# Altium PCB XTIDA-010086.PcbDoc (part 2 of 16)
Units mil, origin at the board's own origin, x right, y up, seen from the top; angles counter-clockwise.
Board outline 14763.78 x 8267.72 mil, 6 copper layers (Top Layer, GND Layer, Signal Layer 1, Signal Layer 2, Power Layer, Bottom Layer), stack 62 mil thick; 1933 components, 1002 nets, 4886 pads, 6482 vias.
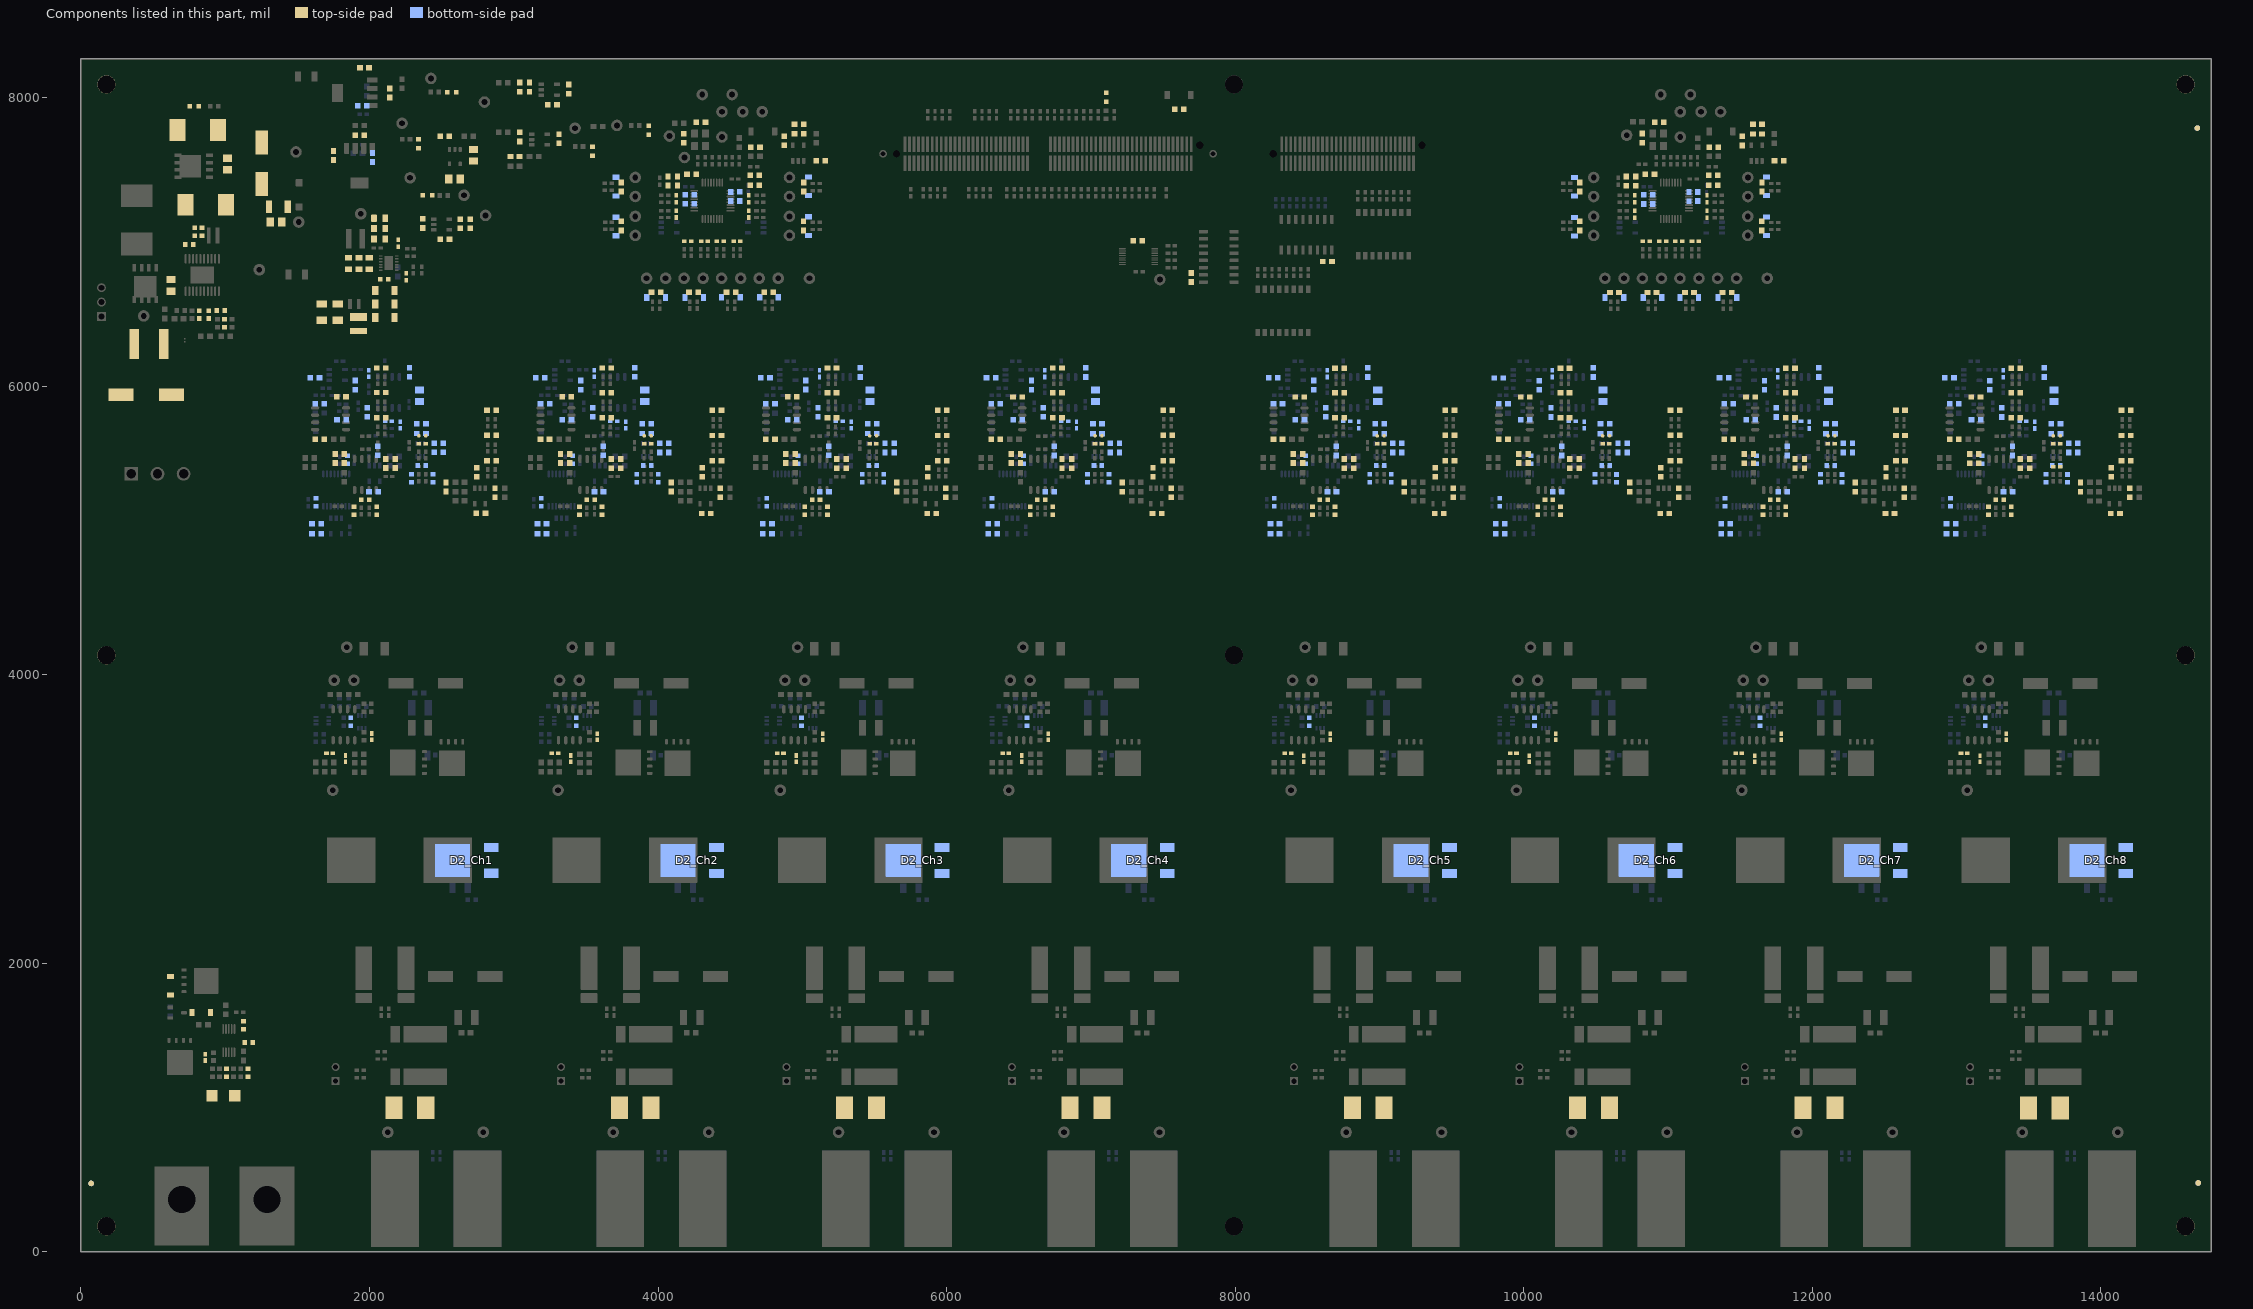
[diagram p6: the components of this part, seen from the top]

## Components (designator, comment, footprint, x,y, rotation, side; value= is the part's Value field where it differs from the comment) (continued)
C16_Ch8 "GCM155R71E103KA37D" 0402 13693.7,5442.01 r180 top value=0.01uF (schematic designator C16)
C17_Ch1 "GCM155R71E103KA37D" 0402 2366,5601.05 r180 top value=0.01uF (schematic designator C17)
C17_Ch2 "GCM155R71E103KA37D" 0402 3928,5600.97 r180 top value=0.01uF (schematic designator C17)
C17_Ch3 "GCM155R71E103KA37D" 0402 5490,5600.89 r180 top value=0.01uF (schematic designator C17)
C17_Ch4 "GCM155R71E103KA37D" 0402 7052,5600.81 r180 top value=0.01uF (schematic designator C17)
C17_Ch5 "GCM155R71E103KA37D" 0402 9007.7,5600.73 r180 top value=0.01uF (schematic designator C17)
C17_Ch6 "GCM155R71E103KA37D" 0402 10569.7,5600.65 r180 top value=0.01uF (schematic designator C17)
C17_Ch7 "GCM155R71E103KA37D" 0402 12131.7,5600.57 r180 top value=0.01uF (schematic designator C17)
C17_Ch8 "GCM155R71E103KA37D" 0402 13693.7,5600.5 r180 top value=0.01uF (schematic designator C17)
C18_Ch1 "Capacitor" 0603 2180,5463.05 r270 top value=1uF (schematic designator C18)
C18_Ch2 "Capacitor" 0603 3742,5462.97 r270 top value=1uF (schematic designator C18)
C18_Ch3 "Capacitor" 0603 5304,5462.89 r270 top value=1uF (schematic designator C18)
C18_Ch4 "Capacitor" 0603 6866,5462.81 r270 top value=1uF (schematic designator C18)
C18_Ch5 "Capacitor" 0603 8821.7,5462.73 r270 top value=1uF (schematic designator C18)
C18_Ch6 "Capacitor" 0603 10383.7,5462.65 r270 top value=1uF (schematic designator C18)
C18_Ch7 "Capacitor" 0603 11945.7,5462.57 r270 top value=1uF (schematic designator C18)
C18_Ch8 "Capacitor" 0603 13507.7,5462.5 r270 top value=1uF (schematic designator C18)
C19_Ch1 "GRM1885C1H102JA01D" 0603L 1971,5212.05 r0 top value=1000pF (schematic designator C19)
C19_Ch2 "GRM1885C1H102JA01D" 0603L 3533,5211.97 r0 top value=1000pF (schematic designator C19)
C19_Ch3 "GRM1885C1H102JA01D" 0603L 5095,5211.89 r0 top value=1000pF (schematic designator C19)
C19_Ch4 "GRM1885C1H102JA01D" 0603L 6657,5211.81 r0 top value=1000pF (schematic designator C19)
C19_Ch5 "GRM1885C1H102JA01D" 0603L 8612.7,5211.73 r0 top value=1000pF (schematic designator C19)
C19_Ch6 "GRM1885C1H102JA01D" 0603L 10174.7,5211.65 r0 top value=1000pF (schematic designator C19)
C19_Ch7 "GRM1885C1H102JA01D" 0603L 11736.7,5211.57 r0 top value=1000pF (schematic designator C19)
C19_Ch8 "GRM1885C1H102JA01D" 0603L 13298.7,5211.5 r0 top value=1000pF (schematic designator C19)
C20_Ch1 "Capacitor" 0603 2114,5463.05 r270 top value=0.1uF (schematic designator C20)
C20_Ch2 "Capacitor" 0603 3676,5462.97 r270 top value=0.1uF (schematic designator C20)
C20_Ch3 "Capacitor" 0603 5238,5462.89 r270 top value=0.1uF (schematic designator C20)
C20_Ch4 "Capacitor" 0603 6800,5462.81 r270 top value=0.1uF (schematic designator C20)
C20_Ch5 "Capacitor" 0603 8755.7,5462.73 r270 top value=0.1uF (schematic designator C20)
C20_Ch6 "Capacitor" 0603 10317.7,5462.65 r270 top value=0.1uF (schematic designator C20)
C20_Ch7 "Capacitor" 0603 11879.7,5462.57 r270 top value=0.1uF (schematic designator C20)
C20_Ch8 "Capacitor" 0603 13441.7,5462.5 r270 top value=0.1uF (schematic designator C20)
C21_Ch1 "GRM1885C1H101JA01D" 0603L 2050.2,5135.25 r90 top value=DNP (schematic designator C21)
C21_Ch2 "GRM1885C1H101JA01D" 0603L 3612.2,5135.17 r90 top value=DNP (schematic designator C21)
C21_Ch3 "GRM1885C1H101JA01D" 0603L 5174.2,5135.09 r90 top value=DNP (schematic designator C21)
C21_Ch4 "GRM1885C1H101JA01D" 0603L 6736.2,5135.01 r90 top value=DNP (schematic designator C21)
C21_Ch5 "GRM1885C1H101JA01D" 0603L 8691.91,5134.93 r90 top value=DNP (schematic designator C21)
C21_Ch6 "GRM1885C1H101JA01D" 0603L 10253.91,5134.85 r90 top value=DNP (schematic designator C21)
C21_Ch7 "GRM1885C1H101JA01D" 0603L 11815.91,5134.77 r90 top value=DNP (schematic designator C21)
C21_Ch8 "GRM1885C1H101JA01D" 0603L 13377.91,5134.7 r90 top value=DNP (schematic designator C21)
C22_Ch1 "GRM1885C1H101JA01D" 0603L 1893.2,5135.25 r270 top value=DNP (schematic designator C22)
C22_Ch2 "GRM1885C1H101JA01D" 0603L 3455.2,5135.17 r270 top value=DNP (schematic designator C22)
C22_Ch3 "GRM1885C1H101JA01D" 0603L 5017.2,5135.09 r270 top value=DNP (schematic designator C22)
C22_Ch4 "GRM1885C1H101JA01D" 0603L 6579.2,5135.01 r270 top value=DNP (schematic designator C22)
C22_Ch5 "GRM1885C1H101JA01D" 0603L 8534.91,5134.93 r270 top value=DNP (schematic designator C22)
C22_Ch6 "GRM1885C1H101JA01D" 0603L 10096.91,5134.85 r270 top value=DNP (schematic designator C22)
C22_Ch7 "GRM1885C1H101JA01D" 0603L 11658.91,5134.77 r270 top value=DNP (schematic designator C22)
C22_Ch8 "GRM1885C1H101JA01D" 0603L 13220.91,5134.7 r270 top value=DNP (schematic designator C22)
C23_Ch1 "Capacitor" 0603 1826,5498.05 r270 top value=0.1uF (schematic designator C23)
C23_Ch2 "Capacitor" 0603 3388,5497.97 r270 top value=0.1uF (schematic designator C23)
C23_Ch3 "Capacitor" 0603 4950,5497.89 r270 top value=0.1uF (schematic designator C23)
C23_Ch4 "Capacitor" 0603 6512,5497.81 r270 top value=0.1uF (schematic designator C23)
C23_Ch5 "Capacitor" 0603 8467.7,5497.73 r270 top value=0.1uF (schematic designator C23)
C23_Ch6 "Capacitor" 0603 10029.7,5497.65 r270 top value=0.1uF (schematic designator C23)
C23_Ch7 "Capacitor" 0603 11591.7,5497.57 r270 top value=0.1uF (schematic designator C23)
C23_Ch8 "Capacitor" 0603 13153.7,5497.5 r270 top value=0.1uF (schematic designator C23)
C24_Ch1 "Capacitor" 0603 1762,5498.05 r270 top value=1uF (schematic designator C24)
C24_Ch2 "Capacitor" 0603 3324,5497.97 r270 top value=1uF (schematic designator C24)
C24_Ch3 "Capacitor" 0603 4886,5497.89 r270 top value=1uF (schematic designator C24)
C24_Ch4 "Capacitor" 0603 6448,5497.81 r270 top value=1uF (schematic designator C24)
C24_Ch5 "Capacitor" 0603 8403.7,5497.73 r270 top value=1uF (schematic designator C24)
C24_Ch6 "Capacitor" 0603 9965.7,5497.65 r270 top value=1uF (schematic designator C24)
C24_Ch7 "Capacitor" 0603 11527.7,5497.57 r270 top value=1uF (schematic designator C24)
C24_Ch8 "Capacitor" 0603 13089.7,5497.5 r270 top value=1uF (schematic designator C24)
C25_Ch1 "C0603C103J3GECAUTO" 0603 2082,5780.05 r0 top value=0.01uF (schematic designator C25)
C25_Ch2 "C0603C103J3GECAUTO" 0603 3644,5779.97 r0 top value=0.01uF (schematic designator C25)
C25_Ch3 "C0603C103J3GECAUTO" 0603 5206,5779.89 r0 top value=0.01uF (schematic designator C25)
C25_Ch4 "C0603C103J3GECAUTO" 0603 6768,5779.81 r0 top value=0.01uF (schematic designator C25)
C25_Ch5 "C0603C103J3GECAUTO" 0603 8723.7,5779.73 r0 top value=0.01uF (schematic designator C25)
C25_Ch6 "C0603C103J3GECAUTO" 0603 10285.7,5779.65 r0 top value=0.01uF (schematic designator C25)
C25_Ch7 "C0603C103J3GECAUTO" 0603 11847.7,5779.57 r0 top value=0.01uF (schematic designator C25)
C25_Ch8 "C0603C103J3GECAUTO" 0603 13409.7,5779.5 r0 top value=0.01uF (schematic designator C25)
C26_Ch1 "C0603C103J3GECAUTO" 0603 2082,5955.05 r0 top value=0.01uF (schematic designator C26)
C26_Ch2 "C0603C103J3GECAUTO" 0603 3644,5954.97 r0 top value=0.01uF (schematic designator C26)
C26_Ch3 "C0603C103J3GECAUTO" 0603 5206,5954.89 r0 top value=0.01uF (schematic designator C26)
C26_Ch4 "C0603C103J3GECAUTO" 0603 6768,5954.81 r0 top value=0.01uF (schematic designator C26)
C26_Ch5 "C0603C103J3GECAUTO" 0603 8723.7,5954.73 r0 top value=0.01uF (schematic designator C26)
C26_Ch6 "C0603C103J3GECAUTO" 0603 10285.7,5954.65 r0 top value=0.01uF (schematic designator C26)
C26_Ch7 "C0603C103J3GECAUTO" 0603 11847.7,5954.57 r0 top value=0.01uF (schematic designator C26)
C26_Ch8 "C0603C103J3GECAUTO" 0603 13409.7,5954.5 r0 top value=0.01uF (schematic designator C26)
C27_Ch1 "C0603C103J3GECAUTO" 0603 2082,6125.05 r0 top value=0.01uF (schematic designator C27)
C27_Ch2 "C0603C103J3GECAUTO" 0603 3644,6124.97 r0 top value=0.01uF (schematic designator C27)
C27_Ch3 "C0603C103J3GECAUTO" 0603 5206,6124.89 r0 top value=0.01uF (schematic designator C27)
C27_Ch4 "C0603C103J3GECAUTO" 0603 6768,6124.81 r0 top value=0.01uF (schematic designator C27)
C27_Ch5 "C0603C103J3GECAUTO" 0603 8723.7,6124.73 r0 top value=0.01uF (schematic designator C27)
C27_Ch6 "C0603C103J3GECAUTO" 0603 10285.7,6124.65 r0 top value=0.01uF (schematic designator C27)
C27_Ch7 "C0603C103J3GECAUTO" 0603 11847.7,6124.57 r0 top value=0.01uF (schematic designator C27)
C27_Ch8 "C0603C103J3GECAUTO" 0603 13409.7,6124.5 r0 top value=0.01uF (schematic designator C27)
C28_Ch1 "C0603C103J3GECAUTO" 0603 3744.87,7379.63 r270 top value=0.01uF (schematic designator C28)
C28_Ch2 "C0603C103J3GECAUTO" 0603 3986.75,6649.05 r0 top value=0.01uF (schematic designator C28)
C28_Ch3 "C0603C103J3GECAUTO" 0603 4506.61,6649.05 r0 top value=0.01uF (schematic designator C28)
C28_Ch4 "C0603C103J3GECAUTO" 0603 5008.42,7110.03 r90 top value=0.01uF (schematic designator C28)
C28_Ch5 "C0603C103J3GECAUTO" 0603 10386.58,7379.32 r270 top value=0.01uF (schematic designator C28)
C28_Ch6 "C0603C103J3GECAUTO" 0603 10628.45,6648.73 r0 top value=0.01uF (schematic designator C28)
C28_Ch7 "C0603C103J3GECAUTO" 0603 11148.31,6648.73 r0 top value=0.01uF (schematic designator C28)
C28_Ch8 "C0603C103J3GECAUTO" 0603 11650.12,7109.71 r90 top value=0.01uF (schematic designator C28)
C29_Ch1 "Capacitor" 0603 2029,5268.05 r0 bottom value=0.1uF (schematic designator C29)
C29_Ch2 "Capacitor" 0603 3591,5267.97 r0 bottom value=0.1uF (schematic designator C29)
C29_Ch3 "Capacitor" 0603 5153,5267.89 r0 bottom value=0.1uF (schematic designator C29)
C29_Ch4 "Capacitor" 0603 6715,5267.81 r0 bottom value=0.1uF (schematic designator C29)
C29_Ch5 "Capacitor" 0603 8670.7,5267.73 r0 bottom value=0.1uF (schematic designator C29)
C29_Ch6 "Capacitor" 0603 10232.7,5267.65 r0 bottom value=0.1uF (schematic designator C29)
C29_Ch7 "Capacitor" 0603 11794.7,5267.57 r0 bottom value=0.1uF (schematic designator C29)
C29_Ch8 "Capacitor" 0603 13356.7,5267.5 r0 bottom value=0.1uF (schematic designator C29)
C30_Ch1 "Capacitor" 0603 2360,5671.05 r180 bottom value=0.1uF (schematic designator C30)
C30_Ch2 "Capacitor" 0603 3922,5670.97 r180 bottom value=0.1uF (schematic designator C30)
C30_Ch3 "Capacitor" 0603 5484,5670.89 r180 bottom value=0.1uF (schematic designator C30)
C30_Ch4 "Capacitor" 0603 7046,5670.81 r180 bottom value=0.1uF (schematic designator C30)
C30_Ch5 "Capacitor" 0603 9001.7,5670.73 r180 bottom value=0.1uF (schematic designator C30)
C30_Ch6 "Capacitor" 0603 10563.7,5670.65 r180 bottom value=0.1uF (schematic designator C30)
C30_Ch7 "Capacitor" 0603 12125.7,5670.57 r180 bottom value=0.1uF (schematic designator C30)
C30_Ch8 "Capacitor" 0603 13687.7,5670.5 r180 bottom value=0.1uF (schematic designator C30)
C31_Ch1 "Capacitor" 0603 2360,5738.05 r180 bottom value=1uF (schematic designator C31)
C31_Ch2 "Capacitor" 0603 3922,5737.97 r180 bottom value=1uF (schematic designator C31)
C31_Ch3 "Capacitor" 0603 5484,5737.89 r180 bottom value=1uF (schematic designator C31)
C31_Ch4 "Capacitor" 0603 7046,5737.81 r180 bottom value=1uF (schematic designator C31)
C31_Ch5 "Capacitor" 0603 9001.7,5737.73 r180 bottom value=1uF (schematic designator C31)
C31_Ch6 "Capacitor" 0603 10563.7,5737.65 r180 bottom value=1uF (schematic designator C31)
C31_Ch7 "Capacitor" 0603 12125.7,5737.57 r180 bottom value=1uF (schematic designator C31)
C31_Ch8 "Capacitor" 0603 13687.7,5737.5 r180 bottom value=1uF (schematic designator C31)
C32_Ch1 "GRM1885C1H102JA01D" 0603L 2363,5449.05 r180 bottom value=1000pF (schematic designator C32)
C32_Ch2 "GRM1885C1H102JA01D" 0603L 3925,5448.97 r180 bottom value=1000pF (schematic designator C32)
C32_Ch3 "GRM1885C1H102JA01D" 0603L 5487,5448.89 r180 bottom value=1000pF (schematic designator C32)
C32_Ch4 "GRM1885C1H102JA01D" 0603L 7049,5448.81 r180 bottom value=1000pF (schematic designator C32)
C32_Ch5 "GRM1885C1H102JA01D" 0603L 9004.7,5448.73 r180 bottom value=1000pF (schematic designator C32)
C32_Ch6 "GRM1885C1H102JA01D" 0603L 10566.7,5448.65 r180 bottom value=1000pF (schematic designator C32)
C32_Ch7 "GRM1885C1H102JA01D" 0603L 12128.7,5448.57 r180 bottom value=1000pF (schematic designator C32)
C32_Ch8 "GRM1885C1H102JA01D" 0603L 13690.7,5448.5 r180 bottom value=1000pF (schematic designator C32)
C33_Ch1 "Capacitor" 0603 2059,5551.05 r90 bottom value=0.1uF (schematic designator C33)
C33_Ch2 "Capacitor" 0603 3621,5550.97 r90 bottom value=0.1uF (schematic designator C33)
C33_Ch3 "Capacitor" 0603 5183,5550.89 r90 bottom value=0.1uF (schematic designator C33)
C33_Ch4 "Capacitor" 0603 6745,5550.81 r90 bottom value=0.1uF (schematic designator C33)
C33_Ch5 "Capacitor" 0603 8700.7,5550.73 r90 bottom value=0.1uF (schematic designator C33)
C33_Ch6 "Capacitor" 0603 10262.7,5550.65 r90 bottom value=0.1uF (schematic designator C33)
C33_Ch7 "Capacitor" 0603 11824.7,5550.57 r90 bottom value=0.1uF (schematic designator C33)
C33_Ch8 "Capacitor" 0603 13386.7,5550.5 r90 bottom value=0.1uF (schematic designator C33)
C34_Ch1 "Capacitor" 0603 2278,6095.05 r90 bottom value=0.1uF (schematic designator C34)
C34_Ch2 "Capacitor" 0603 3840,6094.97 r90 bottom value=0.1uF (schematic designator C34)
C34_Ch3 "Capacitor" 0603 5402,6094.89 r90 bottom value=0.1uF (schematic designator C34)
C34_Ch4 "Capacitor" 0603 6964,6094.81 r90 bottom value=0.1uF (schematic designator C34)
C34_Ch5 "Capacitor" 0603 8919.7,6094.73 r90 bottom value=0.1uF (schematic designator C34)
C34_Ch6 "Capacitor" 0603 10481.7,6094.65 r90 bottom value=0.1uF (schematic designator C34)
C34_Ch7 "Capacitor" 0603 12043.7,6094.57 r90 bottom value=0.1uF (schematic designator C34)
C34_Ch8 "Capacitor" 0603 13605.7,6094.5 r90 bottom value=0.1uF (schematic designator C34)
C35_Ch1 "GRM1885C1H101JA01D" 0603L 2291,5361.05 r90 bottom value=DNP (schematic designator C35)
C35_Ch2 "GRM1885C1H101JA01D" 0603L 3853,5360.97 r90 bottom value=DNP (schematic designator C35)
C35_Ch3 "GRM1885C1H101JA01D" 0603L 5415,5360.89 r90 bottom value=DNP (schematic designator C35)
C35_Ch4 "GRM1885C1H101JA01D" 0603L 6977,5360.81 r90 bottom value=DNP (schematic designator C35)
C35_Ch5 "GRM1885C1H101JA01D" 0603L 8932.7,5360.73 r90 bottom value=DNP (schematic designator C35)
C35_Ch6 "GRM1885C1H101JA01D" 0603L 10494.7,5360.65 r90 bottom value=DNP (schematic designator C35)
C35_Ch7 "GRM1885C1H101JA01D" 0603L 12056.7,5360.57 r90 bottom value=DNP (schematic designator C35)
C35_Ch8 "GRM1885C1H101JA01D" 0603L 13618.7,5360.5 r90 bottom value=DNP (schematic designator C35)
C36_Ch1 "GRM1885C1H101JA01D" 0603L 2440,5360.05 r270 bottom value=DNP (schematic designator C36)
C36_Ch2 "GRM1885C1H101JA01D" 0603L 4002,5359.97 r270 bottom value=DNP (schematic designator C36)
C36_Ch3 "GRM1885C1H101JA01D" 0603L 5564,5359.89 r270 bottom value=DNP (schematic designator C36)
C36_Ch4 "GRM1885C1H101JA01D" 0603L 7126,5359.81 r270 bottom value=DNP (schematic designator C36)
C36_Ch5 "GRM1885C1H101JA01D" 0603L 9081.7,5359.73 r270 bottom value=DNP (schematic designator C36)
C36_Ch6 "GRM1885C1H101JA01D" 0603L 10643.7,5359.65 r270 bottom value=DNP (schematic designator C36)
C36_Ch7 "GRM1885C1H101JA01D" 0603L 12205.7,5359.57 r270 bottom value=DNP (schematic designator C36)
C36_Ch8 "GRM1885C1H101JA01D" 0603L 13767.7,5359.5 r270 bottom value=DNP (schematic designator C36)
C37_Ch1 "885012205044" 0402 1995,6086.67 r90 bottom value=1000pF (schematic designator C37)
C37_Ch2 "885012205044" 0402 3557,6086.59 r90 bottom value=1000pF (schematic designator C37)
C37_Ch3 "885012205044" 0402 5119,6086.51 r90 bottom value=1000pF (schematic designator C37)
C37_Ch4 "885012205044" 0402 6681,6086.43 r90 bottom value=1000pF (schematic designator C37)
C37_Ch5 "885012205044" 0402 8636.7,6086.35 r90 bottom value=1000pF (schematic designator C37)
C37_Ch6 "885012205044" 0402 10198.7,6086.28 r90 bottom value=1000pF (schematic designator C37)
C37_Ch7 "885012205044" 0402 11760.7,6086.2 r90 bottom value=1000pF (schematic designator C37)
C37_Ch8 "885012205044" 0402 13322.7,6086.12 r90 bottom value=1000pF (schematic designator C37)
C38_Ch1 "885012205044" 0402 2132,5756.05 r0 bottom value=1000pF (schematic designator C38)
C38_Ch2 "885012205044" 0402 3694,5755.97 r0 bottom value=1000pF (schematic designator C38)
C38_Ch3 "885012205044" 0402 5256,5755.89 r0 bottom value=1000pF (schematic designator C38)
C38_Ch4 "885012205044" 0402 6818,5755.81 r0 bottom value=1000pF (schematic designator C38)
C38_Ch5 "885012205044" 0402 8773.7,5755.73 r0 bottom value=1000pF (schematic designator C38)
C38_Ch6 "885012205044" 0402 10335.7,5755.65 r0 bottom value=1000pF (schematic designator C38)
C38_Ch7 "885012205044" 0402 11897.7,5755.57 r0 bottom value=1000pF (schematic designator C38)
C38_Ch8 "885012205044" 0402 13459.7,5755.5 r0 bottom value=1000pF (schematic designator C38)
C39_Ch1 "Capacitor" 0603 2512.56,5571.7 r90 bottom value=1uF (schematic designator C39)
C39_Ch2 "Capacitor" 0603 4074.56,5571.62 r90 bottom value=1uF (schematic designator C39)
C39_Ch3 "Capacitor" 0603 5636.56,5571.54 r90 bottom value=1uF (schematic designator C39)
C39_Ch4 "Capacitor" 0603 7198.56,5571.46 r90 bottom value=1uF (schematic designator C39)
C39_Ch5 "Capacitor" 0603 9154.26,5571.39 r90 bottom value=1uF (schematic designator C39)
C39_Ch6 "Capacitor" 0603 10716.26,5571.31 r90 bottom value=1uF (schematic designator C39)
C39_Ch7 "Capacitor" 0603 12278.26,5571.23 r90 bottom value=1uF (schematic designator C39)
C39_Ch8 "Capacitor" 0603 13840.26,5571.15 r90 bottom value=1uF (schematic designator C39)
C40_Ch1 "Capacitor" 0603 1985,5818.05 r270 bottom value=0.1uF (schematic designator C40)
C40_Ch2 "Capacitor" 0603 3547,5817.97 r270 bottom value=0.1uF (schematic designator C40)
C40_Ch3 "Capacitor" 0603 5109,5817.89 r270 bottom value=0.1uF (schematic designator C40)
C40_Ch4 "Capacitor" 0603 6671,5817.81 r270 bottom value=0.1uF (schematic designator C40)
C40_Ch5 "Capacitor" 0603 8626.7,5817.73 r270 bottom value=0.1uF (schematic designator C40)
C40_Ch6 "Capacitor" 0603 10188.7,5817.65 r270 bottom value=0.1uF (schematic designator C40)
C40_Ch7 "Capacitor" 0603 11750.7,5817.57 r270 bottom value=0.1uF (schematic designator C40)
C40_Ch8 "Capacitor" 0603 13312.7,5817.5 r270 bottom value=0.1uF (schematic designator C40)
C41_Ch1 "GRM155R71H122KA01D" 0402 2214,5730.05 r270 bottom value=1200pF (schematic designator C41)
C41_Ch2 "GRM155R71H122KA01D" 0402 3776,5729.97 r270 bottom value=1200pF (schematic designator C41)
C41_Ch3 "GRM155R71H122KA01D" 0402 5338,5729.89 r270 bottom value=1200pF (schematic designator C41)
C41_Ch4 "GRM155R71H122KA01D" 0402 6900,5729.81 r270 bottom value=1200pF (schematic designator C41)
C41_Ch5 "GRM155R71H122KA01D" 0402 8855.7,5729.73 r270 bottom value=1200pF (schematic designator C41)
C41_Ch6 "GRM155R71H122KA01D" 0402 10417.7,5729.65 r270 bottom value=1200pF (schematic designator C41)
C41_Ch7 "GRM155R71H122KA01D" 0402 11979.7,5729.57 r270 bottom value=1200pF (schematic designator C41)
C41_Ch8 "GRM155R71H122KA01D" 0402 13541.7,5729.5 r270 bottom value=1200pF (schematic designator C41)
C42_Ch1 "GRM2195C1H752JA01D" 0805_HV 2346,5933.05 r270 bottom value=7500pF (schematic designator C42)
C42_Ch2 "GRM2195C1H752JA01D" 0805_HV 3908,5932.97 r270 bottom value=7500pF (schematic designator C42)
C42_Ch3 "GRM2195C1H752JA01D" 0805_HV 5470,5932.89 r270 bottom value=7500pF (schematic designator C42)
C42_Ch4 "GRM2195C1H752JA01D" 0805_HV 7032,5932.81 r270 bottom value=7500pF (schematic designator C42)
C42_Ch5 "GRM2195C1H752JA01D" 0805_HV 8987.7,5932.73 r270 bottom value=7500pF (schematic designator C42)
C42_Ch6 "GRM2195C1H752JA01D" 0805_HV 10549.7,5932.65 r270 bottom value=7500pF (schematic designator C42)
C42_Ch7 "GRM2195C1H752JA01D" 0805_HV 12111.7,5932.57 r270 bottom value=7500pF (schematic designator C42)
C42_Ch8 "GRM2195C1H752JA01D" 0805_HV 13673.7,5932.5 r270 bottom value=7500pF (schematic designator C42)
C43_Ch1 "Capacitor" 0603 2449,5571.7 r90 bottom value=0.1uF (schematic designator C43)
C43_Ch2 "Capacitor" 0603 4011,5571.62 r90 bottom value=0.1uF (schematic designator C43)
C43_Ch3 "Capacitor" 0603 5573,5571.54 r90 bottom value=0.1uF (schematic designator C43)
C43_Ch4 "Capacitor" 0603 7135,5571.46 r90 bottom value=0.1uF (schematic designator C43)
C43_Ch5 "Capacitor" 0603 9090.7,5571.39 r90 bottom value=0.1uF (schematic designator C43)
C43_Ch6 "Capacitor" 0603 10652.7,5571.31 r90 bottom value=0.1uF (schematic designator C43)
C43_Ch7 "Capacitor" 0603 12214.7,5571.23 r90 bottom value=0.1uF (schematic designator C43)
C43_Ch8 "Capacitor" 0603 13776.7,5571.15 r90 bottom value=0.1uF (schematic designator C43)
C44_Ch1 "Capacitor" 0603 1655,5631.7 r0 top value=0.1uF (schematic designator C44)
C44_Ch2 "Capacitor" 0603 3217,5631.62 r0 top value=0.1uF (schematic designator C44)
C44_Ch3 "Capacitor" 0603 4779,5631.54 r0 top value=0.1uF (schematic designator C44)
C44_Ch4 "Capacitor" 0603 6341,5631.46 r0 top value=0.1uF (schematic designator C44)
C44_Ch5 "Capacitor" 0603 8296.7,5631.39 r0 top value=0.1uF (schematic designator C44)
C44_Ch6 "Capacitor" 0603 9858.7,5631.31 r0 top value=0.1uF (schematic designator C44)
C44_Ch7 "Capacitor" 0603 11420.7,5631.23 r0 top value=0.1uF (schematic designator C44)
C44_Ch8 "Capacitor" 0603 12982.7,5631.15 r0 top value=0.1uF (schematic designator C44)
C45_Ch1 "Capacitor" 0603 2744.6,5403.17 r90 top value=0.1uF (schematic designator C45)
C45_Ch2 "Capacitor" 0603 4306.6,5403.09 r90 top value=0.1uF (schematic designator C45)
C45_Ch3 "Capacitor" 0603 5868.6,5403.01 r90 top value=0.1uF (schematic designator C45)
C45_Ch4 "Capacitor" 0603 7430.6,5402.93 r90 top value=0.1uF (schematic designator C45)
C45_Ch5 "Capacitor" 0603 9386.3,5402.85 r90 top value=0.1uF (schematic designator C45)
C45_Ch6 "Capacitor" 0603 10948.3,5402.77 r90 top value=0.1uF (schematic designator C45)
C45_Ch7 "Capacitor" 0603 12510.3,5402.69 r90 top value=0.1uF (schematic designator C45)
C45_Ch8 "Capacitor" 0603 14072.3,5402.62 r90 top value=0.1uF (schematic designator C45)
C46_Ch1 "06031C102JAT2A" 0603 1806.79,5766.59 r0 bottom value=1000pF (schematic designator C46)
C46_Ch2 "06031C102JAT2A" 0603 3368.79,5766.51 r0 bottom value=1000pF (schematic designator C46)
C46_Ch3 "06031C102JAT2A" 0603 4930.79,5766.43 r0 bottom value=1000pF (schematic designator C46)
C46_Ch4 "06031C102JAT2A" 0603 6492.79,5766.35 r0 bottom value=1000pF (schematic designator C46)
C46_Ch5 "06031C102JAT2A" 0603 8448.49,5766.28 r0 bottom value=1000pF (schematic designator C46)
C46_Ch6 "06031C102JAT2A" 0603 10010.49,5766.2 r0 bottom value=1000pF (schematic designator C46)
C46_Ch7 "06031C102JAT2A" 0603 11572.49,5766.12 r0 bottom value=1000pF (schematic designator C46)
C46_Ch8 "06031C102JAT2A" 0603 13134.49,5766.04 r0 bottom value=1000pF (schematic designator C46)
C47_Ch1 "Capacitor" 0603 1806,5924.7 r180 top value=0.1uF (schematic designator C47)
C47_Ch2 "Capacitor" 0603 3368,5924.62 r180 top value=0.1uF (schematic designator C47)
C47_Ch3 "Capacitor" 0603 4930,5924.54 r180 top value=0.1uF (schematic designator C47)
C47_Ch4 "Capacitor" 0603 6492,5924.46 r180 top value=0.1uF (schematic designator C47)
C47_Ch5 "Capacitor" 0603 8447.7,5924.39 r180 top value=0.1uF (schematic designator C47)
C47_Ch6 "Capacitor" 0603 10009.7,5924.31 r180 top value=0.1uF (schematic designator C47)
C47_Ch7 "Capacitor" 0603 11571.7,5924.23 r180 top value=0.1uF (schematic designator C47)
C47_Ch8 "Capacitor" 0603 13133.7,5924.15 r180 top value=0.1uF (schematic designator C47)
C48_Ch1 "C0603C103J3GECAUTO" 0603 2846.65,5482.08 r180 top value=0.01uF (schematic designator C48)
C48_Ch2 "C0603C103J3GECAUTO" 0603 4408.2,5481.54 r180 top value=0.01uF (schematic designator C48)
C48_Ch3 "C0603C103J3GECAUTO" 0603 5970.2,5481.46 r180 top value=0.01uF (schematic designator C48)
C48_Ch4 "C0603C103J3GECAUTO" 0603 7532.25,5481.93 r180 top value=0.01uF (schematic designator C48)
C48_Ch5 "C0603C103J3GECAUTO" 0603 9487.94,5482.24 r180 top value=0.01uF (schematic designator C48)
C48_Ch6 "C0603C103J3GECAUTO" 0603 11048.95,5481.77 r180 top value=0.01uF (schematic designator C48)
C48_Ch7 "C0603C103J3GECAUTO" 0603 12610.95,5481.69 r180 top value=0.01uF (schematic designator C48)
C48_Ch8 "C0603C103J3GECAUTO" 0603 14173.95,5481.62 r180 top value=0.01uF (schematic designator C48)
C49_Ch1 "C0603C103J3GECAUTO" 0603 2846.65,5658.08 r180 top value=0.01uF (schematic designator C49)
C49_Ch2 "C0603C103J3GECAUTO" 0603 4408.2,5657.54 r180 top value=0.01uF (schematic designator C49)
C49_Ch3 "C0603C103J3GECAUTO" 0603 5970.2,5657.46 r180 top value=0.01uF (schematic designator C49)
C49_Ch4 "C0603C103J3GECAUTO" 0603 7532.25,5657.93 r180 top value=0.01uF (schematic designator C49)
C49_Ch5 "C0603C103J3GECAUTO" 0603 9487.94,5658.24 r180 top value=0.01uF (schematic designator C49)
C49_Ch6 "C0603C103J3GECAUTO" 0603 11048.95,5657.77 r180 top value=0.01uF (schematic designator C49)
C49_Ch7 "C0603C103J3GECAUTO" 0603 12610.95,5657.69 r180 top value=0.01uF (schematic designator C49)
C49_Ch8 "C0603C103J3GECAUTO" 0603 14173.95,5657.62 r180 top value=0.01uF (schematic designator C49)
C50_Ch1 "C0603C103J3GECAUTO" 0603 2846.65,5832.08 r180 top value=0.01uF (schematic designator C50)
C50_Ch2 "C0603C103J3GECAUTO" 0603 4408.2,5831.54 r180 top value=0.01uF (schematic designator C50)
C50_Ch3 "C0603C103J3GECAUTO" 0603 5970.2,5831.46 r180 top value=0.01uF (schematic designator C50)
C50_Ch4 "C0603C103J3GECAUTO" 0603 7532.25,5831.93 r180 top value=0.01uF (schematic designator C50)
C50_Ch5 "C0603C103J3GECAUTO" 0603 9487.94,5832.24 r180 top value=0.01uF (schematic designator C50)
C50_Ch6 "C0603C103J3GECAUTO" 0603 11048.95,5831.77 r180 top value=0.01uF (schematic designator C50)
C50_Ch7 "C0603C103J3GECAUTO" 0603 12610.95,5831.69 r180 top value=0.01uF (schematic designator C50)
C50_Ch8 "C0603C103J3GECAUTO" 0603 14173.95,5831.62 r180 top value=0.01uF (schematic designator C50)
C51_Ch1 "C0603C103J3GECAUTO" 0603 3744.87,7110.03 r90 top value=0.01uF (schematic designator C51)
C51_Ch2 "C0603C103J3GECAUTO" 0603 4246.68,6649.05 r180 top value=0.01uF (schematic designator C51)
C51_Ch3 "C0603C103J3GECAUTO" 0603 4767.1,6649.05 r180 top value=0.01uF (schematic designator C51)
C51_Ch4 "C0603C103J3GECAUTO" 0603 5008.98,7379.63 r270 top value=0.01uF (schematic designator C51)
C51_Ch5 "C0603C103J3GECAUTO" 0603 10386.58,7109.71 r90 top value=0.01uF (schematic designator C51)
C51_Ch6 "C0603C103J3GECAUTO" 0603 10888.38,6648.73 r180 top value=0.01uF (schematic designator C51)
C51_Ch7 "C0603C103J3GECAUTO" 0603 11408.8,6648.73 r180 top value=0.01uF (schematic designator C51)
C51_Ch8 "C0603C103J3GECAUTO" 0603 11650.68,7379.32 r270 top value=0.01uF (schematic designator C51)
C52_Ch1 "Capacitor" 0603 2530.54,5300.3 r90 top value=1uF (schematic designator C52)
C52_Ch2 "Capacitor" 0603 4092.54,5300.22 r90 top value=1uF (schematic designator C52)
C52_Ch3 "Capacitor" 0603 5654.54,5300.14 r90 top value=1uF (schematic designator C52)
C52_Ch4 "Capacitor" 0603 7216.54,5300.06 r90 top value=1uF (schematic designator C52)
C52_Ch5 "Capacitor" 0603 9172.24,5299.98 r90 top value=1uF (schematic designator C52)
C52_Ch6 "Capacitor" 0603 10734.24,5299.91 r90 top value=1uF (schematic designator C52)
C52_Ch7 "Capacitor" 0603 12296.24,5299.83 r90 top value=1uF (schematic designator C52)
C52_Ch8 "Capacitor" 0603 13858.24,5299.75 r90 top value=1uF (schematic designator C52)
C53_Ch1 "Capacitor" 0603 2772.6,5117.17 r180 top value=0.1uF (schematic designator C53)
C53_Ch2 "Capacitor" 0603 4334.6,5117.09 r180 top value=0.1uF (schematic designator C53)
C53_Ch3 "Capacitor" 0603 5896.6,5117.01 r180 top value=0.1uF (schematic designator C53)
C53_Ch4 "Capacitor" 0603 7458.6,5116.93 r180 top value=0.1uF (schematic designator C53)
C53_Ch5 "Capacitor" 0603 9414.3,5116.85 r180 top value=0.1uF (schematic designator C53)
C53_Ch6 "Capacitor" 0603 10976.3,5116.77 r180 top value=0.1uF (schematic designator C53)
C53_Ch7 "Capacitor" 0603 12538.3,5116.69 r180 top value=0.1uF (schematic designator C53)
C53_Ch8 "Capacitor" 0603 14100.3,5116.62 r180 top value=0.1uF (schematic designator C53)
C54_Ch1 "Capacitor" 0603 2870.54,5260.68 r90 top value=0.1uF (schematic designator C54)
C54_Ch2 "Capacitor" 0603 4432.54,5260.6 r90 top value=0.1uF (schematic designator C54)
C54_Ch3 "Capacitor" 0603 5994.54,5260.52 r90 top value=0.1uF (schematic designator C54)
C54_Ch4 "Capacitor" 0603 7556.54,5260.44 r90 top value=0.1uF (schematic designator C54)
C54_Ch5 "Capacitor" 0603 9512.24,5260.36 r90 top value=0.1uF (schematic designator C54)
C54_Ch6 "Capacitor" 0603 11074.24,5260.28 r90 top value=0.1uF (schematic designator C54)
C54_Ch7 "Capacitor" 0603 12636.24,5260.2 r90 top value=0.1uF (schematic designator C54)
C54_Ch8 "Capacitor" 0603 14198.24,5260.13 r90 top value=0.1uF (schematic designator C54)
C55_Ch1 "06031C102JAT2A" 0603 1655.21,5878.7 r0 bottom value=1000pF (schematic designator C55)
C55_Ch2 "06031C102JAT2A" 0603 3217.21,5878.62 r0 bottom value=1000pF (schematic designator C55)
C55_Ch3 "06031C102JAT2A" 0603 4779.21,5878.54 r0 bottom value=1000pF (schematic designator C55)
C55_Ch4 "06031C102JAT2A" 0603 6341.21,5878.46 r0 bottom value=1000pF (schematic designator C55)
C55_Ch5 "06031C102JAT2A" 0603 8296.91,5878.39 r0 bottom value=1000pF (schematic designator C55)
C55_Ch6 "06031C102JAT2A" 0603 9858.91,5878.31 r0 bottom value=1000pF (schematic designator C55)
C55_Ch7 "06031C102JAT2A" 0603 11420.91,5878.23 r0 bottom value=1000pF (schematic designator C55)
C55_Ch8 "06031C102JAT2A" 0603 12982.91,5878.15 r0 bottom value=1000pF (schematic designator C55)
C56 "C0603C104J3RACTU" 0603L 1127.33,1571.56 r90 top value=0.1uF
C57 "GRM1885C1H103JA01D" 0603L 1009.04,1241.76 r90 top value=0.01uF
C58 "C0603C105K3RACTU" 0603L 1164.5,1450.5 r0 top value=1uF
C59 "GRM1885C1H103JA01D" 0603L 1157.33,1241.56 r90 top value=0.01uF
C60 "CGA2B2C0G1H100D050BA" 0402 4126.11,7297.51 r270 top value=10pF
C61 "CGA2B2C0G1H100D050BA" 0402 4126.11,7191.77 r270 top value=10pF
C62 "Capacitor" 0603 4232.62,7469.01 r0 top value=0.1uF
C63 "CGA2B2C0G1H100D050BA" 0402 4206.56,7004.39 r0 top value=10pF
C64 "Capacitor" 0603 4297.11,7829.01 r180 top value=0.1uF
C65 "CGA2B2C0G1H100D050BA" 0402 4322.11,7004.39 r0 top value=10pF
C66 "CGA2B2C0G1H100D050BA" 0402 4432.11,7004.39 r0 top value=10pF
C67 "CGA2B2C0G1H100D050BA" 0402 4547.67,7004.39 r0 top value=10pF
C68 "CGA2B2C0G1H100D050BA" 0402 4628.11,7191.77 r90 top value=10pF
C69 "Capacitor" 0603 4189.11,7294.01 r270 bottom value=1uF
C70 "Capacitor" 0603 4251.13,7293.85 r270 bottom value=0.1uF
C71 "CGA2B2C0G1H100D050BA" 0402 4628.11,7297.51 r90 top value=10pF
C72 "Capacitor" 0603 4675.11,7656.01 r180 top value=10pF
C73 "Capacitor" 0603 4135.11,7421.01 r90 top value=0.1uF
C74 "Capacitor" 0603 4069.11,7421.01 r90 top value=1uF
C75 "Capacitor" 0603 4565.11,7314.01 r90 bottom value=1uF
C76 "Capacitor" 0603 4503.1,7313.54 r90 bottom value=0.1uF
C77 "Capacitor" 0603 4671.11,7461.01 r0 top value=0.1uF
C78 "Capacitor" 0603 4671.11,7392.01 r0 top value=1uF
C79 "Capacitor" 0603 4977.84,7813.48 r180 top value=1uF
C80 "Capacitor" 0603 4977.84,7747.48 r180 top value=0.1uF
C81 "CGA2B2C0G1H100D050BA" 0402 10767.82,7297.2 r270 top value=10pF
C82 "CGA2B2C0G1H100D050BA" 0402 10767.82,7191.46 r270 top value=10pF
C83 "Capacitor" 0603 10874.32,7468.7 r0 top value=0.1uF
C84 "CGA2B2C0G1H100D050BA" 0402 10848.26,7004.08 r0 top value=10pF
C85 "Capacitor" 0603 10938.82,7828.7 r180 top value=0.1uF
C86 "CGA2B2C0G1H100D050BA" 0402 10963.82,7004.08 r0 top value=10pF
C87 "CGA2B2C0G1H100D050BA" 0402 11073.82,7004.08 r0 top value=10pF
C88 "CGA2B2C0G1H100D050BA" 0402 11189.37,7004.08 r0 top value=10pF
C89 "CGA2B2C0G1H100D050BA" 0402 11269.82,7191.46 r90 top value=10pF
C90 "Capacitor" 0603 10830.82,7293.7 r270 bottom value=1uF
C91 "Capacitor" 0603 10892.83,7293.54 r270 bottom value=0.1uF
C92 "CGA2B2C0G1H100D050BA" 0402 11269.82,7297.2 r90 top value=10pF
C93 "Capacitor" 0603 11316.82,7655.7 r180 top value=10pF
C94 "Capacitor" 0603 10776.82,7420.7 r90 top value=0.1uF
C95 "Capacitor" 0603 10710.82,7420.7 r90 top value=1uF
C96 "Capacitor" 0603 11206.82,7313.7 r90 bottom value=1uF
C97 "Capacitor" 0603 11144.8,7313.22 r90 bottom value=0.1uF
C98 "Capacitor" 0603 11312.82,7460.7 r0 top value=0.1uF
C99 "Capacitor" 0603 11312.82,7391.7 r0 top value=1uF
C100 "Capacitor" 0603 11619.51,7813.19 r180 top value=1uF
C101 "Capacitor" 0603 11619.92,7746.79 r180 top value=0.1uF
C102 "C0603C105K3RACTU" 0603 3042.03,7726.4 r270 top value=1uF
C103 "C0603C105K3RACTU" 0603 3314.03,7714.4 r270 top value=1uF
C104 "EMK212BB7106MG-T" 0805_HV1 1999,6849 r90 top value=10uF
C105 "C0603C105K3RACTU" 0603 1751,7598 r270 top value=1uF
C106 "EMK212BB7106MG-T" 0805_HV1 1927.5,6849 r90 top value=10uF
C107 "EMK212BB7106MG-T" 0805_HV1 1856,6849 r90 top value=10uF
C108 "C0603C105K3RACTU" 0603 1932.79,7738.53 r0 top value=1uF
C109 "EMVH101ADA220MJA0G" CAPSMT_62_JA0 454.5,5940.7 r0 top value=22uF
C110 "C5750X7S2A106M230KB" 2220_250 472.5,6292.7 r0 top value=10uF
C111 "C2012X7R2A104K125AA" 0805_HV 623.5,6697.7 r90 top value=0.1uF
C112 "GRM188R72A104KA35D" 0603L 751.5,6980.7 r0 top value=0.1uF
C113 "APXA160ARA181MHC0G" CAPSMT_62_HC0 1253.5,7545.7 r270 top value=180uF
C114 "C2012X7R1C225K125AB" 0805_HV 1015.5,7538.7 r270 top value=2.2uF
C115 "GRM1885C2A152JA01D" 0603L 970.5,6522.7 r180 top value=1500pF
C116 "GRM188R72A104KA35D" 0603L 887,6495.7 r270 top value=0.1uF
C117 "C1608C0G2A331J080AA" 0603L 820.5,6495.7 r270 top value=330pF
C118 "GRM188R71E105KA12D" 0603L 789.5,7070.7 r90 top value=1uF
C119 "GRM188R71E105KA12D" 0603L 839.5,7070.7 r90 top value=1uF
C120 "GRM188R71H563KA93D" 0603L 995.71,6435.9 r270 top value=0.056uF
C121 "C2012X7R2A104K125AA" 0805_HV 1352.8,7136.39 r180 top value=0.1uF
C122_Ch1 "C0603C104J3RACTU" 0603L 1871,3674.62 r90 bottom value=0.1uF (schematic designator C122)
C122_Ch2 "C0603C104J3RACTU" 0603L 3433,3674.54 r90 bottom value=0.1uF (schematic designator C122)
C122_Ch3 "C0603C104J3RACTU" 0603L 4995,3674.46 r90 bottom value=0.1uF (schematic designator C122)
C122_Ch4 "C0603C104J3RACTU" 0603L 6557,3674.38 r90 bottom value=0.1uF (schematic designator C122)
C122_Ch5 "C0603C104J3RACTU" 0603L 8512.7,3674.3 r90 bottom value=0.1uF (schematic designator C122)
C122_Ch6 "C0603C104J3RACTU" 0603L 10074.7,3674.23 r90 bottom value=0.1uF (schematic designator C122)
C122_Ch7 "C0603C104J3RACTU" 0603L 11636.7,3674.15 r90 bottom value=0.1uF (schematic designator C122)
C122_Ch8 "C0603C104J3RACTU" 0603L 13198.7,3674.07 r90 bottom value=0.1uF (schematic designator C122)
C123 "Capacitor" 0603 7325,7008.01 r180 top value=0.1uF
C124 "Capacitor" 0603 7696.28,6752.2 r90 top value=1uF
C125 "Capacitor" 0603 8639.2,6862.97 r180 top value=1uF
C126 "C0603C103J3GECAUTO" 0603 7612.02,7918.07 r180 top value=0.01uF
C127 "Capacitor" 0603 4873.61,7700.75 r270 top value=0.1uF
C128 "Capacitor" 0603 11514.01,7699.18 r270 top value=0.1uF
C129 "Capacitor" 0805_HV 2720,7599.32 r270 top value=1uF
C130 "Capacitor" 0805_HV 2589,7436.32 r180 top value=1uF
C131 "06031C103KAT2A" 0603 2370,7127 r90 top value=0.01uF
C132 "06031C102JAT2A" 0603 2523,7017.7 r180 top value=1000pF
C133 "GRM188R71E105KA12D" 0603 2699,7124.7 r270 top value=1uF
C134 "06031C103KAT2A" 0603 2630,7124.7 r270 top value=0.01uF
C135_Ch1 "C0603C104J3RACTU" 0603L 1629.36,5195 r90 bottom value=0.1uF (schematic designator C135)
C135_Ch2 "C0603C104J3RACTU" 0603L 3191.36,5194.92 r90 bottom value=0.1uF (schematic designator C135)
C135_Ch3 "C0603C104J3RACTU" 0603L 4753.36,5194.84 r90 bottom value=0.1uF (schematic designator C135)
C135_Ch4 "C0603C104J3RACTU" 0603L 6315.36,5194.76 r90 bottom value=0.1uF (schematic designator C135)
C135_Ch5 "C0603C104J3RACTU" 0603L 8271.06,5194.69 r90 bottom value=0.1uF (schematic designator C135)
C135_Ch6 "C0603C104J3RACTU" 0603L 9833.06,5194.61 r90 bottom value=0.1uF (schematic designator C135)
C135_Ch7 "C0603C104J3RACTU" 0603L 11395.06,5194.53 r90 bottom value=0.1uF (schematic designator C135)
C135_Ch8 "C0603C104J3RACTU" 0603L 12957.06,5194.45 r90 bottom value=0.1uF (schematic designator C135)
C136_Ch1 "Capacitor" 0603 1634,5045 r180 bottom value=0.1uF (schematic designator C136)
C136_Ch2 "Capacitor" 0603 3196,5044.92 r180 bottom value=0.1uF (schematic designator C136)
C136_Ch3 "Capacitor" 0603 4758,5044.84 r180 bottom value=0.1uF (schematic designator C136)
C136_Ch4 "Capacitor" 0603 6320,5044.76 r180 bottom value=0.1uF (schematic designator C136)
C136_Ch5 "Capacitor" 0603 8275.7,5044.69 r180 bottom value=0.1uF (schematic designator C136)
C136_Ch6 "Capacitor" 0603 9837.7,5044.61 r180 bottom value=0.1uF (schematic designator C136)
C136_Ch7 "Capacitor" 0603 11399.7,5044.53 r180 bottom value=0.1uF (schematic designator C136)
C136_Ch8 "Capacitor" 0603 12961.7,5044.45 r180 bottom value=0.1uF (schematic designator C136)
C137 "C3225X7R1H106M250AC" 1210_280 1368.8,7242.39 r180 top value=10uF
C138 "Capacitor" 0603 3109.53,8072 r270 top value=0.1uF
C139 "GRM188R61E106MA73D" 0603 3042,8072 r270 top value=10uF
C140 "C0603C105K3RACTU" 0603 1966,8206 r180 top value=1uF
C141 "C0603C105K3RACTU" 0603 2142,8031 r270 top value=1uF
C142 "Capacitor" 0603 2021,7583.7 r270 bottom value=0.1uF
C143 "Capacitor" 0603 1950,7943.58 r180 bottom value=0.1uF
C144 "Capacitor" 0603 5128,7561 r0 top value=0.1uF
C145 "Capacitor" 0603 11769.57,7560.81 r0 top value=0.1uF
C146 "Capacitor" 0603 3009,7591 r180 top value=0.1uF
C147 "Capacitor" 0603 2522,7731.39 r180 top value=0.1uF
C148 "Capacitor" 0603 4179,7717.5 r270 top value=0.1uF
C149 "Capacitor" 0603 10820.02,7718.51 r270 top value=0.1uF
C150_Ch1 "Capacitor" 0603 1634,4976.08 r180 bottom value=0.1uF (schematic designator C150)
C150_Ch2 "Capacitor" 0603 3196.21,4975.79 r180 bottom value=0.1uF (schematic designator C150)
C150_Ch3 "Capacitor" 0603 4758.21,4975.71 r180 bottom value=0.1uF (schematic designator C150)
C150_Ch4 "Capacitor" 0603 6320,4975.63 r180 bottom value=0.1uF (schematic designator C150)
C150_Ch5 "Capacitor" 0603 8275.7,4975.55 r180 bottom value=0.1uF (schematic designator C150)
C150_Ch6 "Capacitor" 0603 9837.7,4975.69 r180 bottom value=0.1uF (schematic designator C150)
C150_Ch7 "Capacitor" 0603 11399.91,4975.39 r180 bottom value=0.1uF (schematic designator C150)
C150_Ch8 "Capacitor" 0603 12961.7,4975.53 r180 bottom value=0.1uF (schematic designator C150)
C151_Ch1 "C0603C104J3RACTU" 0603L 1846.98,5489.56 r270 bottom value=0.1uF (schematic designator C151)
C151_Ch2 "C0603C104J3RACTU" 0603L 3408.98,5489.48 r270 bottom value=0.1uF (schematic designator C151)
C151_Ch3 "C0603C104J3RACTU" 0603L 4970.98,5489.4 r270 bottom value=0.1uF (schematic designator C151)
C151_Ch4 "C0603C104J3RACTU" 0603L 6532.98,5489.32 r270 bottom value=0.1uF (schematic designator C151)
C151_Ch5 "C0603C104J3RACTU" 0603L 8488.69,5489.24 r270 bottom value=0.1uF (schematic designator C151)
C151_Ch6 "C0603C104J3RACTU" 0603L 10050.69,5489.17 r270 bottom value=0.1uF (schematic designator C151)
C151_Ch7 "C0603C104J3RACTU" 0603L 11612.69,5489.09 r270 bottom value=0.1uF (schematic designator C151)
C151_Ch8 "C0603C104J3RACTU" 0603L 13174.69,5489.01 r270 bottom value=0.1uF (schematic designator C151)
C152 "EMK316BB7226ML-T" 1206_190 2106.5,6475.98 r0 top value=22uF
C153 "EMK316BB7226ML-T" 1206_190 2106.5,6569.48 r0 top value=22uF
C154 "EMK316BB7226ML-T" 1206_190 2106.5,6662.98 r0 top value=22uF
C155 "EMK107BB7225KA-T" 0603_HV 2102.25,6739.11 r0 top value=2.2uF
C156 "F951C476MBAAQ2" F95_B 1925.5,6428.98 r270 top value=47uF
C157 "GRM319R61E475KA12D" 1206 1669.5,6511.98 r270 top value=4.7uF
C158 "GRM319R61E475KA12D" 1206 1779.5,6511.98 r270 top value=4.7uF
C159 "C1005X5R1C105K050BC" 0402 2201,6989 r270 top value=1uF
C160 "C2012X7S1A226M125AC" 0805_HV1 2071,7020 r0 top value=22uF
C161 "C2012X7S1A226M125AC" 0805_HV1 2071,7091.5 r0 top value=22uF
C162 "C2012X7S1A226M125AC" 0805_HV1 2071,7163 r0 top value=22uF
C163 "GRM188R61E106MA73D" 0603 3380,8058 r270 top value=10uF
C164 "GRM155R71C224KA12D" 0402 2254,6757 r270 top value=0.22uF
C165 "06031C103KAT2A" 0603 3268,7950 r180 top value=0.01uF
C166_Ch1 "Capacitor" 0603 1622,6057 r180 bottom value=0.1uF (schematic designator C166)
C166_Ch2 "Capacitor" 0603 3184.24,6056.68 r180 bottom value=0.1uF (schematic designator C166)
C166_Ch3 "Capacitor" 0603 4744.35,6057.07 r180 bottom value=0.1uF (schematic designator C166)
C166_Ch4 "Capacitor" 0603 6308.24,6056.52 r180 bottom value=0.1uF (schematic designator C166)
C166_Ch5 "Capacitor" 0603 8263.94,6056.44 r180 bottom value=0.1uF (schematic designator C166)
C166_Ch6 "Capacitor" 0603 9826.7,6055.61 r180 bottom value=0.1uF (schematic designator C166)
C166_Ch7 "Capacitor" 0603 11387.94,6056.28 r180 bottom value=0.1uF (schematic designator C166)
C166_Ch8 "Capacitor" 0603 12949.94,6056.2 r180 bottom value=0.1uF (schematic designator C166)
C167_Ch1 "Capacitor" 0603 1902,6007 r270 bottom value=0.1uF (schematic designator C167)
C167_Ch2 "Capacitor" 0603 3464.24,6006.68 r270 bottom value=0.1uF (schematic designator C167)
C167_Ch3 "Capacitor" 0603 5024.35,6007.07 r270 bottom value=0.1uF (schematic designator C167)
C167_Ch4 "Capacitor" 0603 6588.24,6006.52 r270 bottom value=0.1uF (schematic designator C167)
C167_Ch5 "Capacitor" 0603 8543.94,6006.44 r270 bottom value=0.1uF (schematic designator C167)
C167_Ch6 "Capacitor" 0603 10106.7,6005.61 r270 bottom value=0.1uF (schematic designator C167)
C167_Ch7 "Capacitor" 0603 11667.94,6006.28 r270 bottom value=0.1uF (schematic designator C167)
C167_Ch8 "Capacitor" 0603 13229.94,6006.2 r270 bottom value=0.1uF (schematic designator C167)
CS+1_Ch1 "TESTPOINT" TP_25MIL-SMT 2390.5,5655.05 r0 top (schematic designator CS+1)
CS+1_Ch2 "TESTPOINT" TP_25MIL-SMT 3952.5,5654.97 r0 top (schematic designator CS+1)
CS+1_Ch3 "TESTPOINT" TP_25MIL-SMT 5514.5,5654.89 r0 top (schematic designator CS+1)
CS+1_Ch4 "TESTPOINT" TP_25MIL-SMT 7076.5,5654.81 r0 top (schematic designator CS+1)
CS+1_Ch5 "TESTPOINT" TP_25MIL-SMT 9032.2,5654.73 r0 top (schematic designator CS+1)
CS+1_Ch6 "TESTPOINT" TP_25MIL-SMT 10594.2,5654.65 r0 top (schematic designator CS+1)
CS+1_Ch7 "TESTPOINT" TP_25MIL-SMT 12156.2,5654.57 r0 top (schematic designator CS+1)
CS+1_Ch8 "TESTPOINT" TP_25MIL-SMT 13718.2,5654.5 r0 top (schematic designator CS+1)
CS-1_Ch1 "TESTPOINT" TP_25MIL-SMT 2342.5,5655.05 r0 top (schematic designator CS-1)
CS-1_Ch2 "TESTPOINT" TP_25MIL-SMT 3904.5,5654.97 r0 top (schematic designator CS-1)
CS-1_Ch3 "TESTPOINT" TP_25MIL-SMT 5466.5,5654.89 r0 top (schematic designator CS-1)
CS-1_Ch4 "TESTPOINT" TP_25MIL-SMT 7028.5,5654.81 r0 top (schematic designator CS-1)
CS-1_Ch5 "TESTPOINT" TP_25MIL-SMT 8984.2,5654.73 r0 top (schematic designator CS-1)
CS-1_Ch6 "TESTPOINT" TP_25MIL-SMT 10546.2,5654.65 r0 top (schematic designator CS-1)
CS-1_Ch7 "TESTPOINT" TP_25MIL-SMT 12108.2,5654.57 r0 top (schematic designator CS-1)
CS-1_Ch8 "TESTPOINT" TP_25MIL-SMT 13670.2,5654.5 r0 top (schematic designator CS-1)
D1_Ch1 "NSR0240V2T1G" SOD-523 2017.39,3570.31 r90 top value=40V (schematic designator D1)
D1_Ch2 "NSR0240V2T1G" SOD-523 3579.39,3570.23 r90 top value=40V (schematic designator D1)
D1_Ch3 "NSR0240V2T1G" SOD-523 5141.39,3570.15 r90 top value=40V (schematic designator D1)
D1_Ch4 "NSR0240V2T1G" SOD-523 6703.39,3570.07 r90 top value=40V (schematic designator D1)
D1_Ch5 "NSR0240V2T1G" SOD-523 8659.09,3569.99 r90 top value=40V (schematic designator D1)
D1_Ch6 "NSR0240V2T1G" SOD-523 10221.09,3569.91 r90 top value=40V (schematic designator D1)
D1_Ch7 "NSR0240V2T1G" SOD-523 11783.09,3569.83 r90 top value=40V (schematic designator D1)
D1_Ch8 "NSR0240V2T1G" SOD-523 13345.09,3569.76 r90 top value=40V (schematic designator D1)
D2_Ch1 "FERD20H100SB-TR" DPAK 2709.95,2713.09 r180 bottom value=45V (schematic designator D2)
D2_Ch2 "FERD20H100SB-TR" DPAK 4271.95,2713.02 r180 bottom value=45V (schematic designator D2)
D2_Ch3 "FERD20H100SB-TR" DPAK 5833.95,2712.94 r180 bottom value=45V (schematic designator D2)
D2_Ch4 "FERD20H100SB-TR" DPAK 7395.95,2712.86 r180 bottom value=45V (schematic designator D2)
D2_Ch5 "FERD20H100SB-TR" DPAK 9351.65,2712.78 r180 bottom value=45V (schematic designator D2)
D2_Ch6 "FERD20H100SB-TR" DPAK 10913.65,2712.7 r180 bottom value=45V (schematic designator D2)
D2_Ch7 "FERD20H100SB-TR" DPAK 12475.65,2712.62 r180 bottom value=45V (schematic designator D2)
D2_Ch8 "FERD20H100SB-TR" DPAK 14037.65,2712.54 r180 bottom value=45V (schematic designator D2)
D3_Ch1 "NSR0240V2T1G" SOD-523 1834.11,3418.11 r270 top value=40V (schematic designator D3)
D3_Ch2 "NSR0240V2T1G" SOD-523 3396.11,3418.04 r270 top value=40V (schematic designator D3)
D3_Ch3 "NSR0240V2T1G" SOD-523 4958.11,3417.96 r270 top value=40V (schematic designator D3)
D3_Ch4 "NSR0240V2T1G" SOD-523 6520.11,3417.88 r270 top value=40V (schematic designator D3)
D3_Ch5 "NSR0240V2T1G" SOD-523 8475.81,3417.8 r270 top value=40V (schematic designator D3)
D3_Ch6 "NSR0240V2T1G" SOD-523 10037.81,3417.72 r270 top value=40V (schematic designator D3)
D3_Ch7 "NSR0240V2T1G" SOD-523 11599.81,3417.64 r270 top value=40V (schematic designator D3)
D3_Ch8 "NSR0240V2T1G" SOD-523 13161.81,3417.56 r270 top value=40V (schematic designator D3)
D4_Ch1 "NSR0240V2T1G" SOD-523 1724.11,3456.11 r180 top value=40V (schematic designator D4)
D4_Ch2 "NSR0240V2T1G" SOD-523 3286.11,3456.04 r180 top value=40V (schematic designator D4)
D4_Ch3 "NSR0240V2T1G" SOD-523 4848.11,3455.96 r180 top value=40V (schematic designator D4)
D4_Ch4 "NSR0240V2T1G" SOD-523 6410.11,3455.88 r180 top value=40V (schematic designator D4)
D4_Ch5 "NSR0240V2T1G" SOD-523 8365.81,3455.81 r180 top value=40V (schematic designator D4)
D4_Ch6 "NSR0240V2T1G" SOD-523 9927.81,3455.73 r180 top value=40V (schematic designator D4)
D4_Ch7 "NSR0240V2T1G" SOD-523 11489.81,3455.65 r180 top value=40V (schematic designator D4)
D4_Ch8 "NSR0240V2T1G" SOD-523 13051.81,3455.57 r180 top value=40V (schematic designator D4)
D5 "1N4148W-7-F" SOD-123 621,1844 r90 top value=100V
D6 "1N4148W-7-F" SOD-123 835,1659 r180 top value=100V
D7 "NSR0240V2T1G" SOD-523 862.33,1347.56 r270 top value=40V
D8 "SMAJ18A" SMA 987.48,1081.82 r0 top value=18V
D9 "B530C-13-F" SMC 810.5,7774.7 r180 top value=30V
D10 "CDBC5100-G" SMC 865.5,7256.7 r0 top value=100V
D11 "150060VS75000" WL-SMCW_GREEN 786,7939.7 r0 top value=Green
D12 "MMSZ5230B-7-F" SOD-123 3710,7382.53 r90 bottom value=4.7V
D13 "150060VS75000" WL-SMCW_GREEN 2402.5,7321.32 r0 top value=Green
D14 "150060VS75000" WL-SMCW_GREEN 3935.11,7773 r90 top value=Green
D15 "150060VS75000" WL-SMCW_GREEN 3546,7628 r90 top value=Green
D16 "MMSZ5230B-7-F" SOD-123 3710,7106 r270 bottom value=4.7V
D17 "150060VS75000" WL-SMCW_GREEN 2340.06,7679.06 r90 top value=Green
D18 "150060VS75000" WL-SMCW_GREEN 2570,8037.6 r180 top value=Green
D19 "MMSZ5230B-7-F" SOD-123 3986.58,6614.17 r180 bottom value=4.7V
D20 "MMSZ5230B-7-F" SOD-123 4250.71,6614.17 r0 bottom value=4.7V
D21 "MMSZ5230B-7-F" SOD-123 4505.08,6615.54 r180 bottom value=4.7V
D22 "MMSZ5230B-7-F" SOD-123 4769.2,6615.54 r0 bottom value=4.7V
D23 "MMSZ5230B-7-F" SOD-123 5041.93,7108.5 r270 bottom value=4.7V
D24 "MMSZ5230B-7-F" SOD-123 5041.93,7385.03 r90 bottom value=4.7V
D25 "MMSZ5230B-7-F" SOD-123 10352.7,7381.22 r90 bottom value=4.7V
D26 "MMSZ5230B-7-F" SOD-123 10352.7,7104.69 r270 bottom value=4.7V
D27 "MMSZ5230B-7-F" SOD-123 10628.29,6613.86 r180 bottom value=4.7V
D28 "MMSZ5230B-7-F" SOD-123 10892.41,6613.86 r0 bottom value=4.7V
D29 "MMSZ5230B-7-F" SOD-123 11146.78,6615.22 r180 bottom value=4.7V
D30 "MMSZ5230B-7-F" SOD-123 11410.91,6615.22 r0 bottom value=4.7V
D31 "MMSZ5230B-7-F" SOD-123 11683.63,7108.18 r270 bottom value=4.7V
D32 "MMSZ5230B-7-F" SOD-123 11683.63,7384.71 r90 bottom value=4.7V
D33 "150060VS75000" WL-SMCW_GREEN 7104.85,8001 r270 top value=Green
F1_Ch1 "6125FA15A" 6125FA 2280,998 r0 top (schematic designator F1)
F1_Ch2 "6125FA15A" 6125FA 3842,997.92 r0 top (schematic designator F1)
F1_Ch3 "6125FA15A" 6125FA 5404,997.84 r0 top (schematic designator F1)
F1_Ch4 "6125FA15A" 6125FA 6966,997.76 r0 top (schematic designator F1)
F1_Ch5 "6125FA15A" 6125FA 8921.7,997.69 r0 top (schematic designator F1)
F1_Ch6 "6125FA15A" 6125FA 10483.7,997.61 r0 top (schematic designator F1)
F1_Ch7 "6125FA15A" 6125FA 12045.7,997.53 r0 top (schematic designator F1)
F1_Ch8 "6125FA15A" 6125FA 13607.7,997.45 r0 top (schematic designator F1)
FID1 "Fiducial" Fiducial10-20 71,474 r0 top
FID2 "Fiducial" Fiducial10-20 14673.7,477 r0 top
FID3 "Fiducial" Fiducial10-20 14667.7,7787.7 r0 top
FID4 "Fiducial" Fiducial10-20 71,474 r180 bottom
FID5 "Fiducial" Fiducial10-20 14673.7,477 r180 bottom
FID6 "Fiducial" Fiducial10-20 14667.7,7787.7 r180 bottom
H1 "NY PMS 440 0025 PH" "NY PMS 440 0025 PH"#1 177.17,8090.55 r0 top
H2 "NY PMS 440 0025 PH" "NY PMS 440 0025 PH"#1 14586.61,8090.55 r0 top
H3 "NY PMS 440 0025 PH" "NY PMS 440 0025 PH"#1 14586.61,177.17 r0 top
H4 "NY PMS 440 0025 PH" "NY PMS 440 0025 PH"#1 177.17,177.17 r0 top
H5 "NY PMS 440 0025 PH" "NY PMS 440 0025 PH"#1 14586.61,4133.86 r0 top
H6 "NY PMS 440 0025 PH" "NY PMS 440 0025 PH"#2 177.17,4133.86 r0 top
H7 "2205" KEYSTONE_2205 177.17,177.17 r180 bottom
H8 "2205" KEYSTONE_2205 14586.61,177.17 r180 bottom
H9 "2205" KEYSTONE_2205 14586.61,4133.86 r180 bottom
H10 "2205" KEYSTONE_2205 14586.61,8090.55 r180 bottom
H11 "2205" KEYSTONE_2205 177.17,8090.55 r180 bottom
